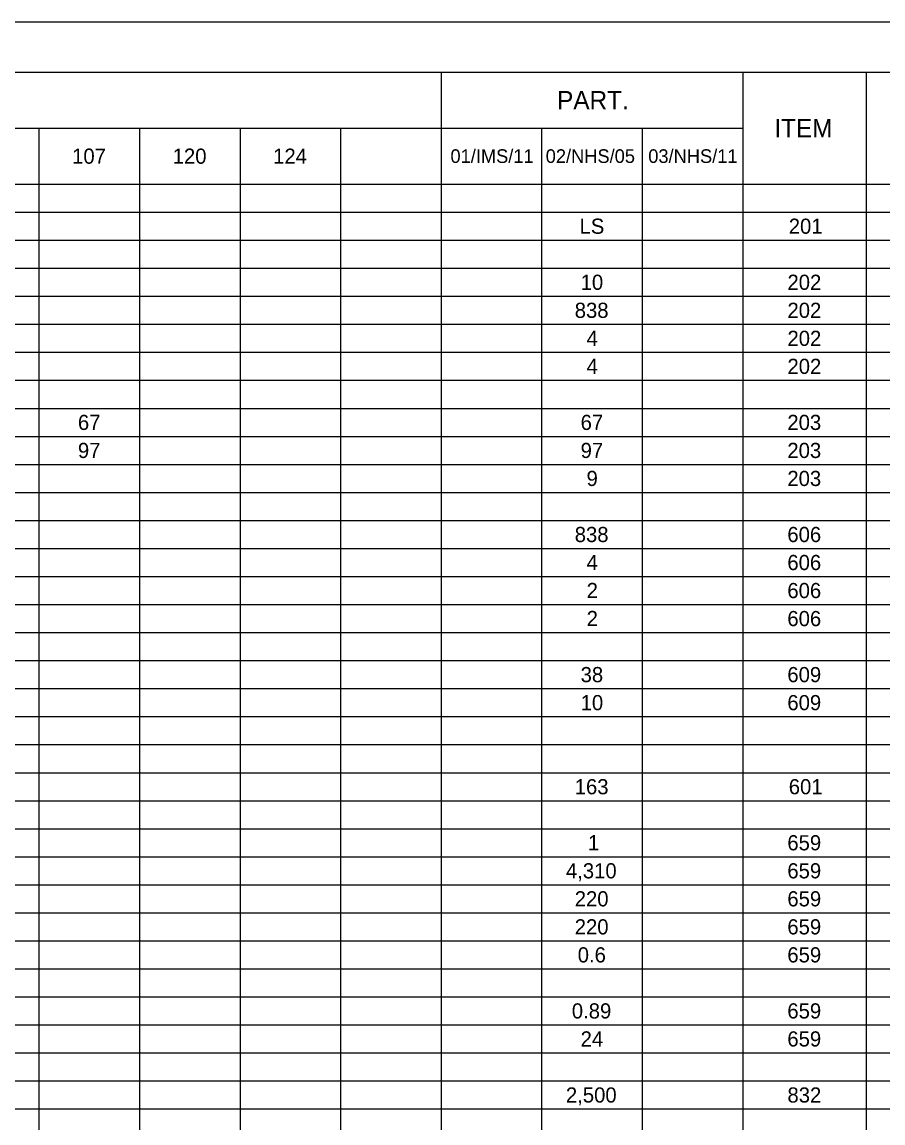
# Model space of a CAD drawing. Extents: x 0 to 34, y 0 to 22.
# Drawn here: x 8.36 to 16.97, y 11 to 22 of the extents above; entities that cross this region are included whole.
import ezdxf

# ---------------------------------------------------------------- set-up
doc = ezdxf.new("R2010")
doc.units = 0
for name, color, linetype in [('SH_Border', 7, 'Continuous'), ('SH_Cut_Line', 7, 'Continuous'), ('SH_Text', 7, 'Continuous')]:
    doc.layers.add(name, color=color, linetype=linetype)

msp = doc.modelspace()

# ---------------------------------------------------------------- linework, layer by layer
at = {"layer": 'SH_Border'}
msp.add_lwpolyline([(1.5, 21.5), (33.5, 21.5), (33.5, 0.5), (1.5, 0.5)], close=True, dxfattribs=at)
at = {"layer": 'SH_Cut_Line'}
msp.add_lwpolyline([(0, 0), (34, 0), (34, 22), (0, 22)], close=True, dxfattribs=at)
at = {"layer": 'SH_Text'}
for p, q in [((1.5, 21.5), (32.004, 21.5)), ((12.552, 21.5), (12.552, 0.5)), ((15.566, 21.5), (15.566, 0.5)), ((16.801, 21.5), (16.801, 0.5)), ((1.5, 20.94), (15.566, 20.94)), ((8.533, 20.94), (8.533, 0.5)), ((9.538, 20.94), (9.538, 0.5)), ((10.542, 20.94), (10.542, 0.5)), ((11.547, 20.94), (11.547, 0.5)), ((13.556, 20.94), (13.556, 0.5)), ((14.561, 20.94), (14.561, 0.5)), ((1.5, 20.38), (32.004, 20.38)), ((1.5, 20.1), (32.004, 20.1)), ((1.5, 19.82), (32.004, 19.82)), ((1.5, 19.54), (32.004, 19.54)), ((1.5, 19.26), (32.004, 19.26)), ((1.5, 18.98), (32.004, 18.98)), ((1.5, 18.7), (32.004, 18.7)), ((1.5, 18.42), (32.004, 18.42)), ((1.5, 18.14), (32.004, 18.14)), ((1.5, 17.86), (32.004, 17.86)), ((1.5, 17.58), (32.004, 17.58)), ((1.5, 17.3), (32.004, 17.3)), ((1.5, 17.02), (32.004, 17.02)), ((1.5, 16.74), (32.004, 16.74)), ((1.5, 16.46), (32.004, 16.46)), ((1.5, 16.18), (32.004, 16.18)), ((1.5, 15.9), (32.004, 15.9)), ((1.5, 15.62), (32.004, 15.62)), ((1.5, 15.34), (32.004, 15.34)), ((1.5, 15.06), (32.004, 15.06)), ((1.5, 14.78), (32.004, 14.78)), ((1.5, 14.5), (32.004, 14.5)), ((1.5, 14.22), (32.004, 14.22)), ((1.5, 13.94), (32.004, 13.94)), ((1.5, 13.66), (32.004, 13.66)), ((1.5, 13.38), (32.004, 13.38)), ((1.5, 13.1), (32.004, 13.1)), ((1.5, 12.82), (32.004, 12.82)), ((1.5, 12.54), (32.004, 12.54)), ((1.5, 12.26), (32.004, 12.26)), ((1.5, 11.98), (32.004, 11.98)), ((1.5, 11.7), (32.004, 11.7)), ((1.5, 11.42), (32.004, 11.42)), ((1.5, 11.14), (32.004, 11.14))]:
    msp.add_line(p, q, dxfattribs=at)

# ---------------------------------------------------------------- texts
for s, height, p in [('PART.', 0.1818, (13.711, 21.129)), ('ITEM', 0.1818, (15.882, 20.849)), ('107', 0.1515, (8.864, 20.584)), ('120', 0.1515, (9.869, 20.584)), ('124', 0.1515, (10.873, 20.584)), ('01/IMS/11', 0.1364, (12.645, 20.592)), ('02/NHS/05', 0.1364, (13.597, 20.592)), ('03/NHS/11', 0.1364, (14.622, 20.592)), ('LS', 0.1515, (13.935, 19.884)), ('201', 0.1515, (16.026, 19.884)), ('10', 0.1515, (13.946, 19.324)), ('202', 0.1515, (16.013, 19.324)), ('838', 0.1515, (13.887, 19.044)), ('202', 0.1515, (16.013, 19.044)), ('4', 0.152, (14.005, 18.764)), ('202', 0.1515, (16.013, 18.764)), ('4', 0.152, (14.005, 18.484)), ('202', 0.1515, (16.013, 18.484)), ('67', 0.1515, (8.922, 17.924)), ('67', 0.1515, (13.946, 17.924)), ('203', 0.1515, (16.012, 17.924)), ('97', 0.1515, (8.922, 17.644)), ('97', 0.1515, (13.946, 17.644)), ('203', 0.1515, (16.012, 17.644)), ('9', 0.152, (14.005, 17.364)), ('203', 0.1515, (16.012, 17.364)), ('838', 0.1515, (13.887, 16.804)), ('606', 0.1515, (16.012, 16.804)), ('4', 0.152, (14.005, 16.524)), ('606', 0.1515, (16.012, 16.524)), ('2', 0.152, (14.006, 16.244)), ('606', 0.1515, (16.012, 16.244)), ('2', 0.152, (14.006, 15.964)), ('606', 0.1515, (16.012, 15.964)), ('38', 0.1515, (13.946, 15.404)), ('609', 0.1515, (16.012, 15.404)), ('10', 0.1515, (13.946, 15.124)), ('609', 0.1515, (16.012, 15.124)), ('163', 0.1515, (13.887, 14.284)), ('601', 0.1515, (16.026, 14.284)), ('1', 0.152, (14.019, 13.724)), ('659', 0.1515, (16.012, 13.724)), ('4,310', 0.1515, (13.799, 13.444)), ('659', 0.1515, (16.012, 13.444)), ('220', 0.1515, (13.887, 13.164)), ('659', 0.1515, (16.012, 13.164)), ('220', 0.1515, (13.887, 12.884)), ('659', 0.1515, (16.012, 12.884)), ('0.6', 0.1515, (13.917, 12.604)), ('659', 0.1515, (16.012, 12.604)), ('0.89', 0.1515, (13.858, 12.044)), ('659', 0.1515, (16.012, 12.044)), ('24', 0.1515, (13.946, 11.764)), ('659', 0.1515, (16.012, 11.764)), ('2,500', 0.1515, (13.799, 11.204)), ('832', 0.1515, (16.013, 11.204))]:
    msp.add_text(s, height=height, dxfattribs=at).set_placement(p)

doc.saveas('drawing.dxf')
